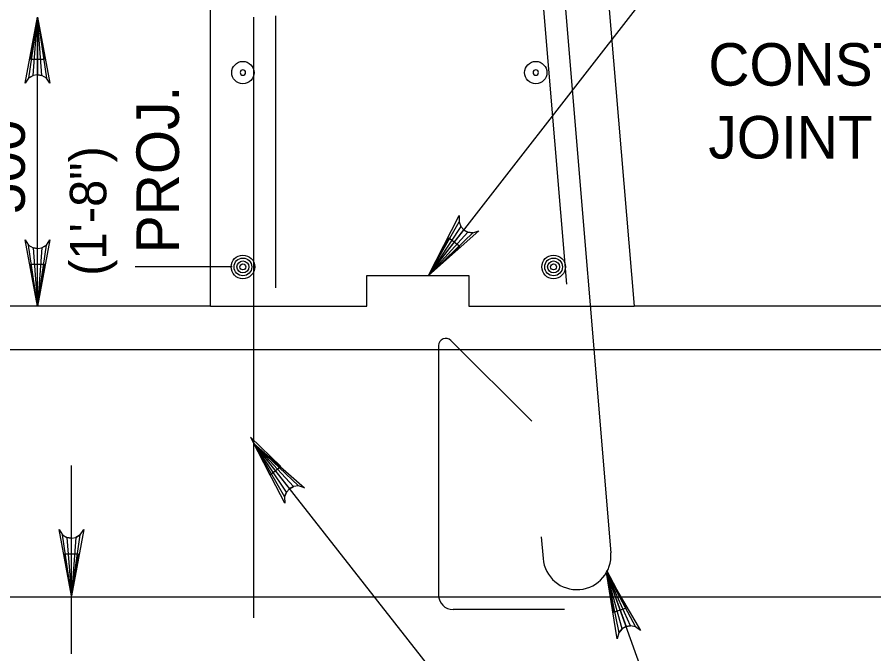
# Model space of a CAD drawing. Extents: x 179 to 454, y -271 to 54.
# Drawn here: x 270.997 to 273.414, y -52.571 to -50.775 of the extents above; entities that cross this region are included whole.
import ezdxf

# ---------------------------------------------------------------- set-up
doc = ezdxf.new("R2010")
doc.units = 0
for name, color, linetype in [('Level 3', 7, 'Continuous'), ('Level 4', 7, 'Continuous'), ('Level 5', 7, 'Continuous'), ('Level 6', 7, 'Continuous'), ('Level 7', 7, 'Continuous'), ('Level 9', 7, 'Continuous')]:
    doc.layers.add(name, color=color, linetype=linetype)

# ---------------------------------------------------------------- blocks, each defined once
blk = doc.blocks.new('B')
at = {"layer": 'Level 3'}
blk.add_circle((0, 0), 0.1066, dxfattribs=at)
for start, end in [(0, 180), (180, 0)]:
    blk.add_arc((0, 0), 0.026, start, end, dxfattribs=at)

msp = doc.modelspace()

# ---------------------------------------------------------------- linework, layer by layer
at = {"layer": 'Level 4'}
for p, q in [((272.1581, -51.5037), (272.7849, -50.6976)), ((271.0548, -51.5902), (271.0548, -50.7751)), ((271.6039, -51.4797), (271.3305, -51.4797)), ((271.6039, -51.4797), (271.3405, -51.4797)), ((271.6654, -51.9777), (272.8484, -53.487)), ((272.6602, -52.3415), (272.8466, -52.86))]:
    msp.add_line(p, q, dxfattribs=at)
for points in [[(271.0548, -50.7751), (271.0897, -50.9615), (271.0798, -50.9472), (271.0673, -50.9397), (271.0548, -50.9376), (271.0423, -50.9397), (271.0298, -50.9472), (271.0199, -50.9615), (271.0548, -50.7751), (271.0298, -50.9472), (271.0423, -50.9397), (271.0548, -50.7751), (271.0548, -50.9376), (271.0673, -50.9397), (271.0548, -50.7751), (271.0798, -50.9472)], [(272.1581, -51.5037), (272.2449, -51.3351), (272.244, -51.3525), (272.2493, -51.366), (272.2578, -51.3754), (272.269, -51.3813), (272.2834, -51.3832), (272.3001, -51.378), (272.1581, -51.5037), (272.2834, -51.3832), (272.269, -51.3813), (272.1581, -51.5037), (272.2578, -51.3754), (272.2493, -51.366), (272.1581, -51.5037), (272.244, -51.3525)], [(271.0548, -51.5902), (271.0199, -51.4037), (271.0298, -51.4181), (271.0423, -51.4255), (271.0548, -51.4277), (271.0673, -51.4255), (271.0798, -51.4181), (271.0897, -51.4037), (271.0548, -51.5902), (271.0798, -51.4181), (271.0673, -51.4255), (271.0548, -51.5902), (271.0548, -51.4277), (271.0423, -51.4255), (271.0548, -51.5902), (271.0298, -51.4181)], [(271.6654, -51.9777), (271.8079, -52.1028), (271.7912, -52.0977), (271.7768, -52.0995), (271.7657, -52.1056), (271.7572, -52.115), (271.7519, -52.1285), (271.7529, -52.1459), (271.6654, -51.9777), (271.7519, -52.1285), (271.7572, -52.115), (271.6654, -51.9777), (271.7657, -52.1056), (271.7768, -52.0995), (271.6654, -51.9777), (271.7912, -52.0977)], [(271.1504, -52.4072), (271.1155, -52.2208), (271.1254, -52.2352), (271.1379, -52.2426), (271.1504, -52.2447), (271.1629, -52.2426), (271.1754, -52.2352), (271.1853, -52.2208), (271.1504, -52.4072), (271.1754, -52.2352), (271.1629, -52.2426), (271.1504, -52.4072), (271.1504, -52.2447), (271.1379, -52.2426), (271.1504, -52.4072), (271.1254, -52.2352)], [(272.6602, -52.3415), (272.7562, -52.5051), (272.7419, -52.4949), (272.7277, -52.4922), (272.7152, -52.4944), (272.7041, -52.5007), (272.6948, -52.5118), (272.6903, -52.5287), (272.6602, -52.3415), (272.6948, -52.5118), (272.7041, -52.5007), (272.6602, -52.3415), (272.7152, -52.4944), (272.7277, -52.4922), (272.6602, -52.3415), (272.7419, -52.4949)]]:
    msp.add_lwpolyline(points, dxfattribs=at)
for points in [[(271.0352, -50.8932), (271.0745, -50.8932), (271.0548, -50.7751)], [(272.2461, -51.4225), (272.215, -51.3983), (272.1581, -51.5037)], [(271.0352, -51.4721), (271.0745, -51.4721), (271.0548, -51.5902)], [(271.7099, -52.0664), (271.7417, -52.0432), (271.656, -51.9596)], [(272.6797, -52.4539), (272.717, -52.4414), (272.6608, -52.3357)]]:
    msp.add_lwpolyline(points, close=True, dxfattribs=at)
at = {"layer": 'Level 5'}
msp.add_line((271.5391, -51.5905), (271.5391, -51.5905), dxfattribs=at)
at = {"layer": 'Level 6'}
for p, q in [((272.4663, -49.8143), (272.6722, -52.2863)), ((272.4054, -49.8244), (272.5474, -51.5287)), ((271.6654, -52.4697), (271.6654, -50.7751)), ((271.7269, -51.5389), (271.7269, -50.7715)), ((272.1864, -51.7017), (272.1864, -52.4052)), ((272.4496, -51.9153), (272.2214, -51.6872)), ((274.7546, -51.7132), (270.4414, -51.7132)), ((271.1504, -52.5712), (271.1504, -52.0403)), ((272.476, -52.2409), (272.4811, -52.3023)), ((270.4411, -52.4105), (274.7549, -52.4105)), ((272.5416, -52.4463), (272.2274, -52.4463))]:
    msp.add_line(p, q, dxfattribs=at)
msp.add_lwpolyline([(271.1307, -52.2891), (271.1701, -52.2891), (271.1504, -52.4072)], close=True, dxfattribs=at)
for centre, radius in [((271.6343, -51.4797), 0.0333), ((271.6343, -51.4797), 0.025), ((272.5108, -51.4797), 0.0333), ((272.5108, -51.4797), 0.025), ((271.6343, -51.4797), 0.0167), ((271.6343, -51.4797), 0.00833), ((272.5108, -51.4797), 0.0167), ((272.5108, -51.4797), 0.00833)]:
    msp.add_circle(centre, radius, dxfattribs=at)
for centre, radius, start, end in [((272.2069, -51.7017), 0.0205, 45, 180), ((272.5767, -52.2943), 0.0959, 184.7636, 4.7636), ((272.2274, -52.4053), 0.041, 180, 270)]:
    msp.add_arc(centre, radius, start, end, dxfattribs=at)
at = {"layer": 'Level 7'}
msp.add_lwpolyline([(271.5428, -51.5902), (271.9841, -51.5902), (271.9841, -51.5037), (272.2717, -51.5037), (272.2717, -51.5902), (272.7378, -51.5902)], dxfattribs=at)
at = {"layer": 'Level 9'}
for p, q in [((271.5428, -51.5902), (271.5428, -46.1403)), ((272.2836, -46.1402), (272.7378, -51.5902)), ((271.5428, -51.5902), (270.3125, -51.5902)), ((274.8834, -51.5902), (272.7378, -51.5902))]:
    msp.add_line(p, q, dxfattribs=at)

# ---------------------------------------------------------------- block references
at = {"layer": 'Level 3', "xscale": 0.29527500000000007, "yscale": 0.29527500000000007, "rotation": 90}
for p in [(271.6343, -50.9315), (272.4606, -50.9315)]:
    msp.add_blockref('B', p, dxfattribs=at)

# ---------------------------------------------------------------- texts
at = {"layer": 'Level 3'}
for s, height, p in [('PROJ.', 0.12, (271.4539, -51.441)), ('500', 0.12, (271.0191, -51.3312)), ('(1\'-8")', 0.10289, (271.249, -51.5048))]:
    msp.add_text(s, height=height, rotation=90, dxfattribs=at).set_placement(p)
at = {"layer": 'Level 4'}
for s, p in [('CONSTR.', (272.9475, -50.9684)), ('JOINT', (272.9475, -51.1739))]:
    msp.add_text(s, height=0.12, dxfattribs=at).set_placement(p)

doc.saveas('drawing.dxf')
